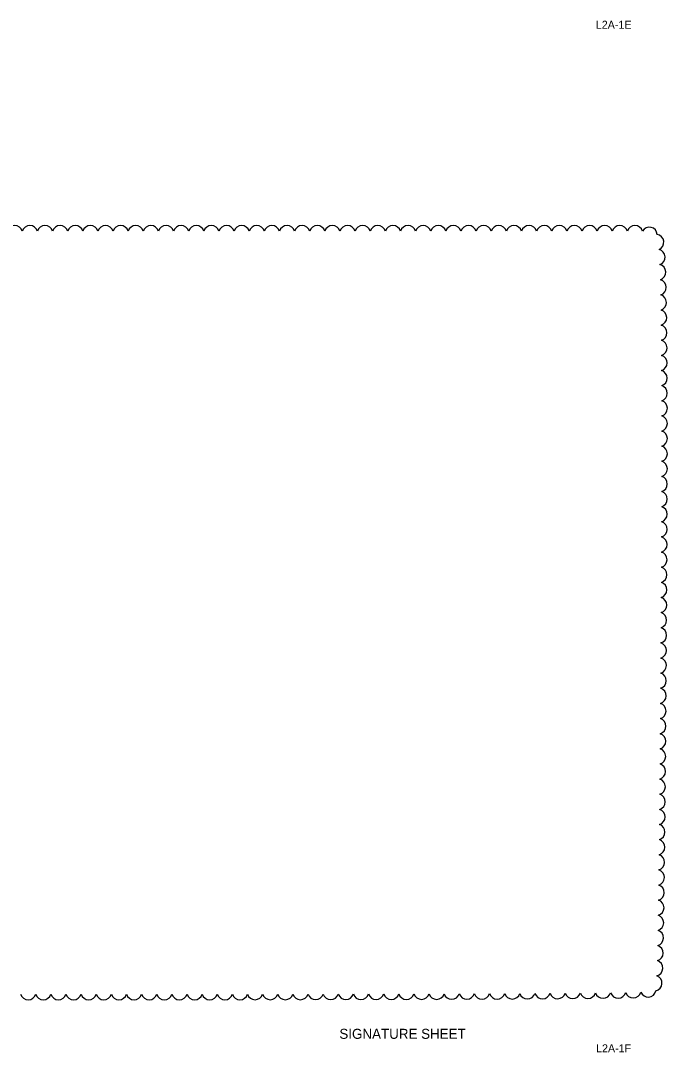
# Model space of a CAD drawing. Extents: x -811 to 10319, y -2309 to 9962.
# Drawn here: x -803.18 to -795.1, y -2270.88 to -2257.99 of the extents above; entities that cross this region are included whole.
import ezdxf

# ---------------------------------------------------------------- set-up
doc = ezdxf.new("R2010")
doc.units = 0
for name, color, linetype in [('PlotBorder_dp', 7, 'Continuous'), ('ScratchEle_dp', 7, 'Continuous'), ('SheetLines_dp', 7, 'Continuous')]:
    doc.layers.add(name, color=color, linetype=linetype)

msp = doc.modelspace()

# ---------------------------------------------------------------- linework, layer by layer
at = {"layer": 'ScratchEle_dp'}
for centre, radius, start, end in [((-803.255, -2260.649), 0.0991, 17.5008, 162.5008), ((-803.066, -2260.649), 0.0991, 17.5, 162.5), ((-802.877, -2260.649), 0.0991, 17.5, 162.5), ((-802.688, -2260.649), 0.0991, 17.5, 162.5), ((-802.499, -2260.649), 0.0991, 17.5, 162.5), ((-802.31, -2260.649), 0.0991, 17.5, 162.5), ((-802.121, -2260.649), 0.0991, 17.5, 162.5), ((-801.932, -2260.649), 0.0991, 17.5, 162.5), ((-801.743, -2260.649), 0.0991, 17.5, 162.5), ((-801.554, -2260.649), 0.0991, 17.5, 162.5), ((-801.365, -2260.649), 0.0991, 17.5, 162.5), ((-801.176, -2260.649), 0.0991, 17.5, 162.5), ((-800.987, -2260.649), 0.0991, 17.5, 162.5), ((-800.798, -2260.649), 0.0991, 17.5, 162.5), ((-800.609, -2260.649), 0.0991, 17.5, 162.5), ((-800.42, -2260.649), 0.0991, 17.5, 162.5), ((-800.231, -2260.649), 0.0991, 17.5, 162.5), ((-800.042, -2260.649), 0.0991, 17.5, 162.5), ((-799.853, -2260.649), 0.0991, 17.5, 162.5), ((-799.664, -2260.649), 0.0991, 17.5, 162.5), ((-799.475, -2260.649), 0.0991, 17.5, 162.5), ((-799.286, -2260.649), 0.0991, 17.5, 162.5), ((-799.097, -2260.649), 0.0991, 17.5, 162.5), ((-798.908, -2260.649), 0.0991, 17.5, 162.5), ((-798.719, -2260.649), 0.0991, 17.5, 162.5), ((-798.53, -2260.649), 0.0991, 17.5, 162.5), ((-798.341, -2260.649), 0.0991, 17.5, 162.5), ((-798.152, -2260.649), 0.0991, 17.5, 162.5), ((-797.963, -2260.649), 0.0991, 17.5, 162.5), ((-797.774, -2260.649), 0.0991, 17.5, 162.5), ((-797.585, -2260.649), 0.0991, 17.5, 162.5), ((-797.396, -2260.649), 0.0991, 17.5, 162.5), ((-797.207, -2260.649), 0.0991, 17.5, 162.5), ((-797.018, -2260.649), 0.0991, 17.5, 162.5), ((-796.829, -2260.649), 0.0991, 17.5, 162.5), ((-796.64, -2260.649), 0.0991, 17.5, 162.5), ((-796.451, -2260.649), 0.0991, 17.5, 162.5), ((-796.262, -2260.649), 0.0991, 17.5, 162.5), ((-796.073, -2260.649), 0.0991, 17.5, 162.5), ((-795.884, -2260.649), 0.0991, 17.5, 162.5), ((-795.695, -2260.649), 0.0991, 17.5, 162.5), ((-795.506, -2260.649), 0.0991, 17.5, 162.5), ((-795.326, -2260.669), 0.099, 4.4162, 149.4162), ((-795.245, -2260.759), 0.0992, 294.7802, 79.7802), ((-795.229, -2260.945), 0.0991, 290.3649, 75.3649), ((-795.221, -2261.133), 0.0991, 289.3839, 74.3839), ((-795.215, -2261.322), 0.0991, 288.8712, 73.8712), ((-795.212, -2261.511), 0.0991, 288.5423, 73.5423), ((-795.208, -2261.7), 0.0991, 288.3081, 73.3081), ((-795.206, -2261.889), 0.0991, 288.1304, 73.1304), ((-795.204, -2262.078), 0.0991, 287.9896, 72.9896), ((-795.203, -2262.266), 0.0991, 287.8744, 72.8744), ((-795.202, -2262.455), 0.0991, 287.778, 72.778), ((-795.201, -2262.644), 0.0991, 287.6956, 72.6956), ((-795.2, -2262.833), 0.0991, 287.6243, 72.6243), ((-795.2, -2263.022), 0.0991, 287.5617, 72.5617), ((-795.2, -2263.211), 0.0991, 287.5062, 72.5062), ((-795.2, -2263.4), 0.0991, 287.4565, 72.4565), ((-795.2, -2263.589), 0.0991, 287.4117, 72.4117), ((-795.201, -2263.778), 0.0991, 287.3711, 72.3711), ((-795.201, -2263.967), 0.0991, 287.3339, 72.3339), ((-795.202, -2264.156), 0.0991, 287.2999, 72.2999), ((-795.202, -2264.345), 0.0991, 287.2684, 72.2684), ((-795.203, -2264.534), 0.0991, 287.2394, 72.2394), ((-795.204, -2264.723), 0.0991, 287.2123, 72.2123), ((-795.205, -2264.912), 0.0991, 287.1871, 72.1871), ((-795.206, -2265.101), 0.0991, 287.1635, 72.1635), ((-795.207, -2265.29), 0.0991, 287.1414, 72.1414), ((-795.209, -2265.479), 0.0991, 287.126, 72.126), ((-795.21, -2265.668), 0.0991, 287.1162, 72.1162), ((-795.211, -2265.857), 0.0991, 287.1058, 72.1058), ((-795.212, -2266.046), 0.0991, 287.0946, 72.0946), ((-795.214, -2266.235), 0.0991, 287.0827, 72.0827), ((-795.215, -2266.424), 0.0991, 287.0698, 72.0698), ((-795.217, -2266.613), 0.0991, 287.0559, 72.0559), ((-795.218, -2266.802), 0.0991, 287.0408, 72.0408), ((-795.22, -2266.991), 0.0991, 287.0244, 72.0244), ((-795.221, -2267.18), 0.0991, 287.0064, 72.0064), ((-795.223, -2267.369), 0.0991, 286.9865, 71.9865), ((-795.225, -2267.558), 0.0991, 286.9645, 71.9645), ((-795.226, -2267.747), 0.0991, 286.94, 71.94), ((-795.228, -2267.936), 0.0991, 286.9123, 71.9123), ((-795.23, -2268.125), 0.0991, 286.8807, 71.8807), ((-795.232, -2268.314), 0.0991, 286.8443, 71.8443), ((-795.235, -2268.503), 0.0991, 286.8016, 71.8016), ((-795.237, -2268.692), 0.0991, 286.7507, 71.7507), ((-795.24, -2268.881), 0.0991, 286.6884, 71.6884), ((-795.242, -2269.07), 0.0991, 286.6098, 71.6098), ((-795.246, -2269.259), 0.0991, 286.5063, 71.5063), ((-795.249, -2269.447), 0.0991, 286.3609, 71.3609), ((-795.253, -2269.636), 0.0991, 286.1344, 71.1344), ((-795.258, -2269.825), 0.0991, 285.7012, 70.7012), ((-795.268, -2270.013), 0.099, 283.7418, 68.7418), ((-803.087, -2270.122), 0.0991, 197.4952, 342.4952), ((-802.898, -2270.122), 0.0991, 197.5007, 342.5007), ((-802.709, -2270.122), 0.0991, 197.5043, 342.5043), ((-802.52, -2270.122), 0.0991, 197.5079, 342.5079), ((-802.331, -2270.122), 0.0991, 197.5117, 342.5117), ((-802.142, -2270.122), 0.0991, 197.5156, 342.5156), ((-801.953, -2270.122), 0.0991, 197.5197, 342.5197), ((-801.764, -2270.121), 0.0991, 197.5239, 342.5239), ((-801.575, -2270.121), 0.0991, 197.5284, 342.5284), ((-801.386, -2270.121), 0.0991, 197.533, 342.533), ((-801.197, -2270.121), 0.0991, 197.5379, 342.5379), ((-801.008, -2270.121), 0.0991, 197.543, 342.543), ((-800.819, -2270.121), 0.0991, 197.5483, 342.5483), ((-800.63, -2270.121), 0.0991, 197.554, 342.554), ((-800.441, -2270.121), 0.0991, 197.5599, 342.5599), ((-800.252, -2270.12), 0.0991, 197.5662, 342.5662), ((-800.063, -2270.12), 0.0991, 197.5729, 342.5729), ((-799.874, -2270.12), 0.0991, 197.5799, 342.5799), ((-799.685, -2270.12), 0.0991, 197.5874, 342.5874), ((-799.496, -2270.119), 0.0991, 197.5954, 342.5954), ((-799.307, -2270.119), 0.0991, 197.604, 342.604), ((-799.118, -2270.119), 0.0991, 197.6131, 342.6131), ((-798.929, -2270.118), 0.0991, 197.623, 342.623), ((-798.74, -2270.118), 0.0991, 197.6337, 342.6337), ((-798.551, -2270.117), 0.0991, 197.6452, 342.6452), ((-798.362, -2270.117), 0.0991, 197.6578, 342.6578), ((-798.173, -2270.116), 0.0991, 197.6716, 342.6716), ((-797.984, -2270.116), 0.0991, 197.6868, 342.6868), ((-797.795, -2270.115), 0.0991, 197.7037, 342.7037), ((-797.606, -2270.114), 0.0991, 197.7225, 342.7225), ((-797.417, -2270.114), 0.0991, 197.7438, 342.7438), ((-797.228, -2270.113), 0.0991, 197.768, 342.768), ((-797.039, -2270.112), 0.0991, 197.796, 342.796), ((-796.85, -2270.111), 0.0991, 197.8288, 342.8288), ((-796.661, -2270.11), 0.0991, 197.8681, 342.8681), ((-796.472, -2270.108), 0.0991, 197.9161, 342.9161), ((-796.283, -2270.107), 0.0991, 197.9767, 342.9767), ((-796.094, -2270.105), 0.0991, 198.0568, 343.0568), ((-795.905, -2270.103), 0.0991, 198.1697, 343.1697), ((-795.716, -2270.101), 0.0991, 198.3466, 343.3466), ((-795.528, -2270.097), 0.0991, 198.6898, 343.6898), ((-795.341, -2270.087), 0.0992, 202.4244, 347.4244)]:
    msp.add_arc(centre, radius, start, end, dxfattribs=at)

# ---------------------------------------------------------------- texts
at = {"layer": 'PlotBorder_dp'}
msp.add_text('       SIGNATURE SHEET         ', height=0.125, dxfattribs=at).set_placement((-799.524, -2270.708))
at = {"layer": 'SheetLines_dp'}
for s, p in [('L2A-1E', (-795.995, -2258.092)), ('L2A-1F', (-795.992, -2270.877))]:
    msp.add_text(s, height=0.1, dxfattribs=at).set_placement(p)

doc.saveas('drawing.dxf')
